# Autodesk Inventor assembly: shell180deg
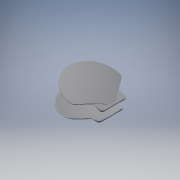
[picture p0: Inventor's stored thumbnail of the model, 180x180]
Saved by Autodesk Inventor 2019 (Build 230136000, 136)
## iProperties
Created: 2021-03
Part Number: shell180deg
Material: 一般
Document SubType Name: Assembly
Designer: kikut
Author: kikut
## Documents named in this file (2)
- F:\openFOAM\shell\shell00\cad\shell180deg.iam
- F:\openFOAM\shell\shell00\cad\shell.ipt
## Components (2 placed, 1 different names)
1. shell:1 — メイト:1, 角度:1
2. shell:2 — 角度:2
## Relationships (3: Angle 2, Mate 1)
- メイト:1 [Mate]: shell:1
- 角度:1 [Angle]: shell:1
- 角度:2 [Angle]: shell:2
